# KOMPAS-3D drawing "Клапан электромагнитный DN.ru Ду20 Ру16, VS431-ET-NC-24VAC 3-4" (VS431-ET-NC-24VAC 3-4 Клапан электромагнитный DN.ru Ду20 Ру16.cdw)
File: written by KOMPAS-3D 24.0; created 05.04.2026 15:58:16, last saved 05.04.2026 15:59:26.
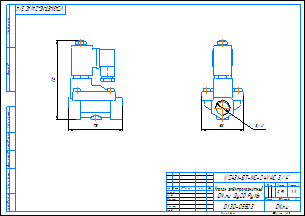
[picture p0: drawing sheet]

Document properties: c3d_UniqueCompID: ef56311e-7521-43dc-8291-0e6108b3d81d; Автор: artio; Класс точности: c; Знак неуказанной шероховатости: Шероховатость не задана; Рассекать на разрезах: Да; Автор: artio; Форматы листов документа: A3; Полное имя файла: VS431-ET-NC-24VAC 3-4 Клапан электромагнитный DN.ru Ду20 Ру16.m3d; Масса: 0.907; Наименование: Клапан электромагнитный DN.ru Ду20 Ру16; Количество листов документа: 1; Примечание: D130-05503

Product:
- Body: Тело 1  | qty 1
    Масса: 1.198355
- Part/product: Клапан электромагнитный DN.ru Ду20 Ру16  | designation VS431-ET-NC-24VAC 3-4
    Масса: 0.907
    Раздел спецификации: Прочие изделия
    Форматы листов документа: A3
    Примечание: D130-05503
    additional columns: ef56311e-7521-43dc-8291-0e6108b3d81d; artio; c; Шероховатость не задана; Да

Views: Вид 1, Спереди, Проекционный вид 2
Referenced files in C:\Users\artio\OneDrive\Рабочий стол\Клапан электромагнитный DN.ru\VS431\VS431-ET-NC\: VS431-ET-NC-24VAC 3-4 Клапан электромагнитный DN.ru Ду20 Ру16.m3d
Referenced files in C:\Users\artio\OneDrive\Рабочий стол\Клапан электромагнитный DN.ru\VS431\VS431-ET-NC\VS431-ET-NC-24VAC\Ду20\: VS431-ET-NC-24VAC 3-4 Клапан электромагнитный DN.ru Ду20 Ру16.cdw, VS431-ET-NC-24VAC 3-4 Клапан электромагнитный DN.ru Ду20 Ру16.m3d
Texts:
  VS431-ET-NC-24VAC 3-4
  Клапан электромагнитный
  DN.ru Ду20 Ру16
  VS431-ET-NC-24VAC 3/4"
  VS431-ET-NC-24VAC 3/4"-
  Клапан электромагнитный DN.ru Ду20 Ру16
  VS431-ET-NC-24VAC 3-4 Клапан электромагнитный DN.ru Ду20 Ру16
Dimensions and other numbers on the sheet: 0; 3; 2; 4; 58; 3/4"; 75; 110; 1:1; 1; 0,91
